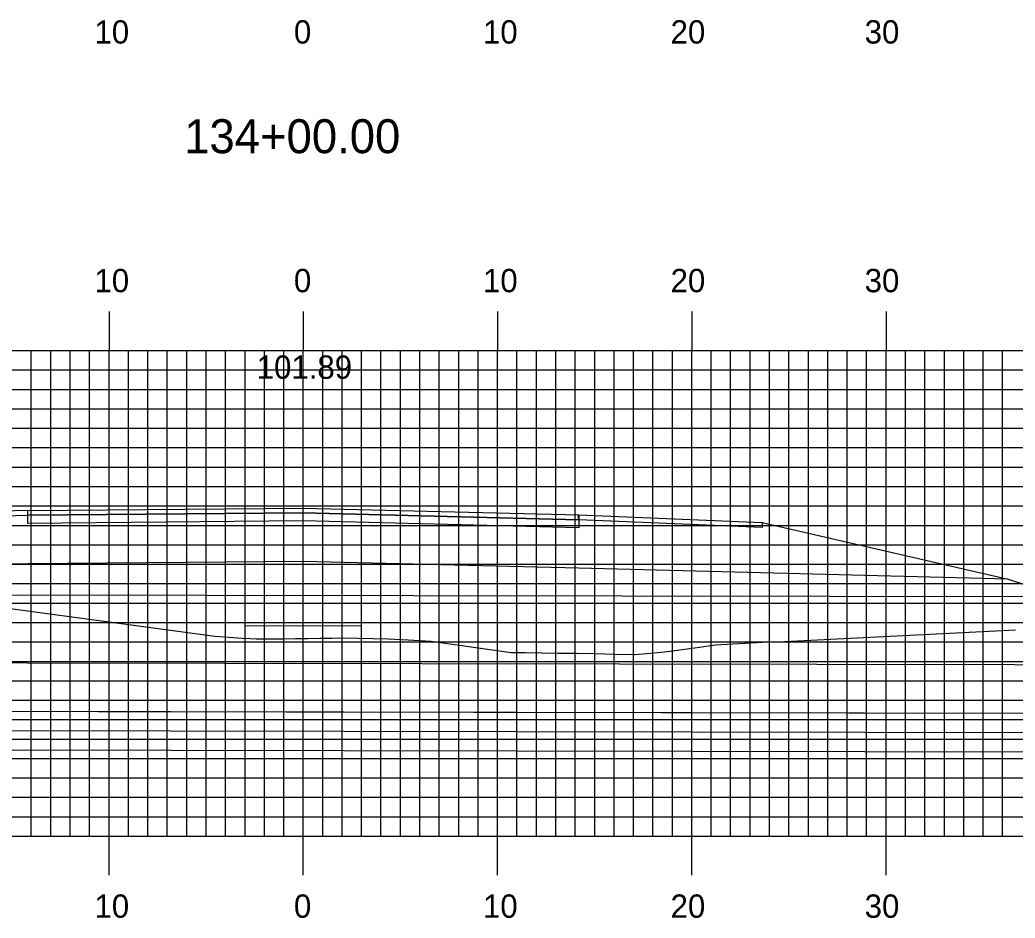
# Model space of a CAD drawing. Extents: x 1774777 to 1775120, y 442591 to 442811.
# Drawn here: x 1774928.1 to 1774979.3, y 442644.4 to 442690.7 of the extents above; entities that cross this region are included whole.
import ezdxf

# ---------------------------------------------------------------- set-up
doc = ezdxf.new("R2010")
doc.units = 0
for name, color, linetype in [('ANNOTATION', 7, 'Continuous'), ('D_Drainage_Culvert', 7, 'Continuous'), ('D_Roadway_Centerline_Text', 7, 'Continuous'), ('D_Roadway_Edge_Shoulder', 7, 'Continuous'), ('D_Roadway_Edge_TW', 7, 'Continuous'), ('D_Roadway_FinishedGrade', 7, 'Continuous'), ('D_Roadway_Pavement', 7, 'Continuous'), ('H_V ANNOTATION', 7, 'Continuous'), ('MAJOR', 7, 'Continuous'), ('MINOR', 7, 'Continuous'), ('S_Roadway_Centerline', 7, 'Continuous')]:
    doc.layers.add(name, color=color, linetype=linetype)

msp = doc.modelspace()

# ---------------------------------------------------------------- linework, layer by layer
at = {"layer": 'ANNOTATION'}
msp.add_lwpolyline([(1774978.969, 442661.903), (1774956.856, 442662.454), (1774942.683, 442662.807), (1774928.511, 442662.681), (1774905.753, 442662.477)], dxfattribs=at)
at = {"layer": 'D_Drainage_Culvert'}
for p, q in [((1774883.795, 442661.172), (1774999.794, 442660.965)), ((1774939.685, 442659.503), (1774945.685, 442659.492)), ((1774883.784, 442655.172), (1774999.784, 442654.965)), ((1774883.784, 442654.179), (1774999.784, 442653.972)), ((1774883.784, 442653.179), (1774999.784, 442652.972))]:
    msp.add_line(p, q, dxfattribs=at)
msp.add_lwpolyline([(1774883.784, 442655.172), (1774999.784, 442654.965), (1774999.784, 442654.971)], dxfattribs=at)
at = {"layer": 'D_Roadway_Edge_Shoulder'}
for points in [[(1774928.508, 442665.431), (1774919.057, 442665.186), (1774919.057, 442664.936), (1774928.508, 442665.181)], [(1774956.86, 442665.205), (1774966.31, 442664.809), (1774966.31, 442664.559), (1774956.86, 442664.955)], [(1774956.862, 442665.204), (1774966.313, 442664.809), (1774966.313, 442664.559), (1774956.862, 442664.954)]]:
    msp.add_lwpolyline(points, close=True, dxfattribs=at)
at = {"layer": 'D_Roadway_Edge_TW'}
msp.add_lwpolyline([(1774928.508, 442665.181), (1774928.508, 442665.431), (1774942.685, 442665.557), (1774956.862, 442665.204), (1774956.862, 442664.954), (1774942.685, 442665.307)], close=True, dxfattribs=at)
at = {"layer": 'D_Roadway_FinishedGrade'}
for p, q in [((1774966.31, 442664.809), (1774978.969, 442661.903)), ((1774978.969, 442661.903), (1774999.784, 442654.965))]:
    msp.add_line(p, q, dxfattribs=at)
msp.add_lwpolyline([(1774887.788, 442657.665), (1775009.789, 442657.447), (1775009.788, 442654.965), (1775009.788, 442652.965)], dxfattribs=at)
at = {"layer": 'D_Roadway_Pavement'}
msp.add_lwpolyline([(1774928.508, 442664.764), (1774928.508, 442665.181), (1774942.685, 442665.307), (1774956.862, 442664.954), (1774956.862, 442664.538), (1774942.685, 442664.891)], close=True, dxfattribs=at)
at = {"layer": 'MAJOR'}
for p, q in [((1774932.685, 442675.669), (1774932.685, 442673.665)), ((1774942.685, 442675.669), (1774942.685, 442673.665)), ((1774952.685, 442675.669), (1774952.685, 442673.665)), ((1774962.685, 442675.669), (1774962.685, 442673.665)), ((1774972.685, 442675.669), (1774972.685, 442673.665)), ((1774802.685, 442673.665), (1775082.685, 442673.665)), ((1774802.685, 442673.665), (1775082.685, 442673.665)), ((1774932.685, 442648.665), (1774932.685, 442673.665)), ((1774942.685, 442648.665), (1774942.685, 442673.665)), ((1774952.685, 442648.665), (1774952.685, 442673.665)), ((1774962.685, 442648.665), (1774962.685, 442673.665)), ((1774972.685, 442648.665), (1774972.685, 442673.665)), ((1774802.685, 442668.665), (1775082.685, 442668.665)), ((1774802.685, 442663.665), (1775082.685, 442663.665)), ((1774802.685, 442658.665), (1775082.685, 442658.665)), ((1774802.685, 442653.665), (1775082.685, 442653.665)), ((1774802.685, 442648.665), (1775082.685, 442648.665)), ((1774802.685, 442648.665), (1775082.685, 442648.665)), ((1774932.685, 442646.661), (1774932.685, 442648.665)), ((1774942.685, 442646.661), (1774942.685, 442648.665)), ((1774952.685, 442646.661), (1774952.685, 442648.665)), ((1774962.685, 442646.661), (1774962.685, 442648.665)), ((1774972.685, 442646.661), (1774972.685, 442648.665))]:
    msp.add_line(p, q, dxfattribs=at)
at = {"layer": 'MINOR'}
for p, q in [((1774928.685, 442648.665), (1774928.685, 442673.665)), ((1774929.685, 442648.665), (1774929.685, 442673.665)), ((1774930.685, 442648.665), (1774930.685, 442673.665)), ((1774931.685, 442648.665), (1774931.685, 442673.665)), ((1774933.685, 442648.665), (1774933.685, 442673.665)), ((1774934.685, 442648.665), (1774934.685, 442673.665)), ((1774935.685, 442648.665), (1774935.685, 442673.665)), ((1774936.685, 442648.665), (1774936.685, 442673.665)), ((1774937.685, 442648.665), (1774937.685, 442673.665)), ((1774938.685, 442648.665), (1774938.685, 442673.665)), ((1774939.685, 442648.665), (1774939.685, 442673.665)), ((1774940.685, 442648.665), (1774940.685, 442673.665)), ((1774941.685, 442648.665), (1774941.685, 442673.665)), ((1774943.685, 442648.665), (1774943.685, 442673.665)), ((1774944.685, 442648.665), (1774944.685, 442673.665)), ((1774945.685, 442648.665), (1774945.685, 442673.665)), ((1774946.685, 442648.665), (1774946.685, 442673.665)), ((1774947.685, 442648.665), (1774947.685, 442673.665)), ((1774948.685, 442648.665), (1774948.685, 442673.665)), ((1774949.685, 442648.665), (1774949.685, 442673.665)), ((1774950.685, 442648.665), (1774950.685, 442673.665)), ((1774951.685, 442648.665), (1774951.685, 442673.665)), ((1774953.685, 442648.665), (1774953.685, 442673.665)), ((1774954.685, 442648.665), (1774954.685, 442673.665)), ((1774955.685, 442648.665), (1774955.685, 442673.665)), ((1774956.685, 442648.665), (1774956.685, 442673.665)), ((1774957.685, 442648.665), (1774957.685, 442673.665)), ((1774958.685, 442648.665), (1774958.685, 442673.665)), ((1774959.685, 442648.665), (1774959.685, 442673.665)), ((1774960.685, 442648.665), (1774960.685, 442673.665)), ((1774961.685, 442648.665), (1774961.685, 442673.665)), ((1774963.685, 442648.665), (1774963.685, 442673.665)), ((1774964.685, 442648.665), (1774964.685, 442673.665)), ((1774965.685, 442648.665), (1774965.685, 442673.665)), ((1774966.685, 442648.665), (1774966.685, 442673.665)), ((1774967.685, 442648.665), (1774967.685, 442673.665)), ((1774968.685, 442648.665), (1774968.685, 442673.665)), ((1774969.685, 442648.665), (1774969.685, 442673.665)), ((1774970.685, 442648.665), (1774970.685, 442673.665)), ((1774971.685, 442648.665), (1774971.685, 442673.665)), ((1774973.685, 442648.665), (1774973.685, 442673.665)), ((1774974.685, 442648.665), (1774974.685, 442673.665)), ((1774975.685, 442648.665), (1774975.685, 442673.665)), ((1774976.685, 442648.665), (1774976.685, 442673.665)), ((1774977.685, 442648.665), (1774977.685, 442673.665)), ((1774978.685, 442648.665), (1774978.685, 442673.665)), ((1774802.685, 442672.665), (1775082.685, 442672.665)), ((1774802.685, 442671.665), (1775082.685, 442671.665)), ((1774802.685, 442670.665), (1775082.685, 442670.665)), ((1774802.685, 442669.665), (1775082.685, 442669.665)), ((1774802.685, 442667.665), (1775082.685, 442667.665)), ((1774802.685, 442666.665), (1775082.685, 442666.665)), ((1774802.685, 442665.665), (1775082.685, 442665.665)), ((1774802.685, 442664.665), (1775082.685, 442664.665)), ((1774802.685, 442662.665), (1775082.685, 442662.665)), ((1774802.685, 442661.665), (1775082.685, 442661.665)), ((1774802.685, 442660.665), (1775082.685, 442660.665)), ((1774802.685, 442659.665), (1775082.685, 442659.665)), ((1774802.685, 442657.665), (1775082.685, 442657.665)), ((1774802.685, 442656.665), (1775082.685, 442656.665)), ((1774802.685, 442655.665), (1775082.685, 442655.665)), ((1774802.685, 442654.665), (1775082.685, 442654.665)), ((1774802.685, 442652.665), (1775082.685, 442652.665)), ((1774802.685, 442651.665), (1775082.685, 442651.665)), ((1774802.685, 442650.665), (1775082.685, 442650.665)), ((1774802.685, 442649.665), (1775082.685, 442649.665))]:
    msp.add_line(p, q, dxfattribs=at)
at = {"layer": 'S_Roadway_Centerline'}
msp.add_lwpolyline([(1774927.104, 442660.452), (1774938.139, 442658.954), (1774938.628, 442658.919), (1774939.097, 442658.887), (1774939.535, 442658.86), (1774939.926, 442658.839), (1774940.256, 442658.826), (1774940.666, 442658.82), (1774941.153, 442658.819), (1774941.7, 442658.824), (1774942.29, 442658.833), (1774942.906, 442658.843), (1774943.531, 442658.854), (1774944.148, 442658.863), (1774944.741, 442658.869), (1774947.058, 442658.82), (1774948.08, 442658.77), (1774949.261, 442658.71), (1774953.388, 442658.124), (1774954.128, 442658.116), (1774954.945, 442658.106), (1774955.829, 442658.094), (1774956.765, 442658.079), (1774957.734, 442658.062), (1774958.708, 442658.042), (1774959.649, 442658.02), (1774959.755, 442658.017), (1774960.566, 442658.081), (1774961.274, 442658.153), (1774961.951, 442658.235), (1774962.558, 442658.318), (1774963.081, 442658.396), (1774963.523, 442658.464), (1774963.894, 442658.522), (1774966.935, 442658.679), (1774967.113, 442658.677), (1774979.352, 442659.292)], dxfattribs=at)

# ---------------------------------------------------------------- texts
at = {"layer": 'D_Roadway_Centerline_Text'}
msp.add_text('101.89', height=1.2, dxfattribs=at).set_placement((1774940.288, 442672.209))
at = {"layer": 'H_V ANNOTATION'}
for s, height, p in [('10', 1.2, (1774931.936, 442689.465)), ('0', 1.2, (1774942.203, 442689.465)), ('10', 1.2, (1774951.936, 442689.465)), ('20', 1.2, (1774961.593, 442689.465)), ('30', 1.2, (1774971.583, 442689.465)), ('134+00.00', 1.75, (1774936.552, 442683.821)), ('10', 1.2, (1774931.936, 442676.665)), ('0', 1.2, (1774942.203, 442676.665)), ('10', 1.2, (1774951.936, 442676.665)), ('20', 1.2, (1774961.593, 442676.665)), ('30', 1.2, (1774971.583, 442676.665)), ('10', 1.2, (1774931.936, 442644.465)), ('0', 1.2, (1774942.203, 442644.465)), ('10', 1.2, (1774951.936, 442644.465)), ('20', 1.2, (1774961.593, 442644.465)), ('30', 1.2, (1774971.583, 442644.465))]:
    msp.add_text(s, height=height, dxfattribs=at).set_placement(p)

doc.saveas('drawing.dxf')
